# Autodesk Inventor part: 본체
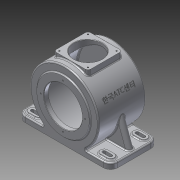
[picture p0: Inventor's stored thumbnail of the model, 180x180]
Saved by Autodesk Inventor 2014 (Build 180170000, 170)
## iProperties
Created: 2015-06
Part Number: 본체
Material: 알루미늄 6061
Document SubType Name: Modeling
Designer: basic
Density: 2.71 g/cm^3
Appearance: 알루미늄 - 평지
Mass: 3237.59 g
Surface Area: 2301.07 cm^2
Volume: 1194.68 cm^3
Author: basic
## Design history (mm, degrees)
sketch "스케치1"
  geometry: L1 (115, 7)-(-115, 7); L2 (-115, 7)-(-115, -7); L3 (-115, -7)-(115, -7); L4 (115, -7)-(115, 7); A1 r 85 centre (0, 78) between (46.733, 7) and (-46.733, 7); 3 further points
  constraints: 8 end point, 2 midpoint, 2 parallel, 2 point on circle, 2 point on line, 2 vertical alignment, 1 centre point, 1 horizontal, 1 horizontal alignment, 1 perpendicular
  dimensions: "d0" = 230 distance of L1.start L1.end; "d1" = 14 distance of L1.end L2.end; "d2" = 170 diameter of A1; "d3" = 85 distance from line of A1.centre L3
extrude "돌출1" new body sketch "스케치1" stored distance "d4" = 118; taper "d5" = 0 deg
sketch "스케치2"
  geometry: C1 r 65 at (0, 78); A1 r 85 centre (0, 78) between (46.733, 7) and (-46.733, 7) reference; 1 further point
  constraints: 1 centre point, 1 coincident
  dimensions: "d6" = 130 diameter of C1
extrude "돌출2" join sketch "스케치2" distance "d7" = 3; taper "d8" = 0 deg
sketch "스케치3"
  geometry: C1 r 65 at (0, -78); A1 r 85 centre (0, -78) between (-46.733, -7) and (46.733, -7) reference; 1 further point
  constraints: 1 centre point, 1 coincident
  dimensions: "d9" = 130 diameter of C1
extrude "돌출3" join sketch "스케치3" distance "d10" = 13; taper "d11" = 0 deg
node "작업 평면1"
sketch "스케치4"
  geometry: L1 (200, 0)-(30, 0) reference; L2 (157.5, -16.5)-(72.5, -16.5); L3 (72.5, -16.5)-(72.5, -101.5); L4 (72.5, -101.5)-(157.5, -101.5); L5 (157.5, -101.5)-(157.5, -16.5); 5 further points
  constraints: 8 end point, 2 midpoint, 2 parallel, 1 horizontal, 1 horizontal alignment, 1 perpendicular, 1 vertical alignment
  dimensions: "d13" = 85 distance of L4.end L3.end; "d14" = 85 distance of L3.end L2.end
extrude "돌출4" join sketch "스케치4" stored distance "d15" = 13; taper "d16" = 0 deg
sketch "스케치5"
  geometry: L1 (68.267, 0)-(68.267, 118) reference; L2 (0, 118)-(68.267, 118) reference; L3 (-161.733, 0)-(-161.733, 118) reference; L4 (68.267, 118)-(-161.733, 118) reference; L5 (68.267, 0)-(68.267, 118) reference; L6 (-161.733, 0)-(68.267, 0) reference; L7 (34.267, 109)-(50.267, 109); L8 (50.267, 91)-(34.267, 91); A1 r 9 centre (50.267, 100) between (50.267, 91) and (50.267, 109); A2 r 9 centre (34.267, 100) between (34.267, 109) and (34.267, 91); 1 further point
  constraints: 4 end point, 4 point on circle, 4 tangent, 2 centre point, 1 horizontal alignment
  dimensions: "d17" = 18 diameter of A1; "d18" = 18 diameter of A2; "d19" = 16 distance of A2.centre A1.centre; "d20" = 18 distance from line of A1.centre L1; "d21" = 18 distance from line of L2 A1.centre
extrude "돌출5" join sketch "스케치5" distance "d22" = 3; taper "d23" = 0 deg
sketch "스케치6"
  geometry: L1 (50.267, 109)-(34.267, 109) reference; L2 (34.267, 104)-(50.267, 104); L3 (50.267, 96)-(34.267, 96); A1 r 9 centre (34.267, 100) between (34.267, 109) and (34.267, 91) reference; A2 r 9 centre (50.267, 100) between (50.267, 91) and (50.267, 109) reference; A3 r 4 centre (50.267, 100) between (50.267, 96) and (50.267, 104); A4 r 4 centre (34.267, 100) between (34.267, 104) and (34.267, 96); 1 further point
  constraints: 4 end point, 4 point on circle, 3 tangent, 2 centre point, 2 coincident, 1 parallel
  dimensions: "d24" = 8 diameter of A3; "d25" = 8 diameter of A4
extrude "돌출6" cut sketch "스케치6" stored distance "d26" = 3; taper "d27" = 0 deg
sketch "스케치7"
  geometry: L1 (115, 7)-(46.733, 7) reference; L2 (-46.733, 7)-(-115, 7) reference; L3 (-115, 7)-(-115, -7) reference; L4 (-115, -7)-(115, -7) reference; L5 (115, -7)-(115, 7) reference; L6 (-109, 7)-(-84.87, 73.297); C1 r 65 at (0, 78) reference; A1 r 85 centre (0, 78) between (46.733, 7) and (-46.733, 7) reference; 1 further point
  constraints: 2 end point, 1 point on circle, 1 point on line
  dimensions: "d28" = 6 distance from line of L3 L6.start; "d29" = 110 deg angle of L2 L6
extrude "돌출7" join sketch "스케치7" stored distance "d30" = 15; taper "d31" = 0 deg
sketch "스케치8"
  geometry: L1 (115, 7)-(46.733, 7) reference; L2 (-46.733, 7)-(-115, 7) reference; L3 (-115, 7)-(-115, -7) reference; L4 (-115, -7)-(115, -7) reference; L5 (115, -7)-(115, 7) reference; C1 r 65 at (0, 78) reference; C2 r 77 at (0, 78); A1 r 85 centre (0, 78) between (46.733, 7) and (-46.733, 7) reference; 1 further point
  constraints: 1 centre point, 1 coincident
  dimensions: "d32" = 154 diameter of C2
extrude "돌출8" cut sketch "스케치8" stored distance "d33" = 102; taper "d34" = 0 deg
sketch "스케치9"
  geometry: C1 r 65 at (0, 0) reference; C2 r 47.5 at (0, 0); 1 further point
  constraints: 1 centre point, 1 coincident
  dimensions: "d35" = 95 diameter of C2
extrude "돌출9" cut sketch "스케치9" distance "d36" = 11; taper "d37" = 0 deg
sketch "스케치10"
  geometry: L1 (7.5, 73.297)-(7.5, 7) reference; L2 (59, 7)-(7.5, 7) reference; L3 (59, 7)-(59, 7) reference; L4 (-59, 7)-(59, 7) reference; L5 (-59, 7)-(-59, 7) reference; L6 (-7.5, 7)-(-59, 7) reference; L7 (-7.5, 7)-(-7.5, 73.297) reference; L8 (-7.5, 73.297)-(7.5, 73.297) reference; L9 (-42.5, 151.612)-(42.5, 151.612) reference; L10 (42.5, 151.612)-(42.5, 151.612) reference; L11 (42.5, 151.612)-(-42.5, 151.612) reference; L12 (-42.5, 151.612)-(-42.5, 151.612) reference; L13 (51, 1)-(51, 155) reference; L14 (-51, 125.5)-(-51, 30.5) reference; L15 (-62, 30.5)-(-62, 125.5) reference; L16 (47.5, 107.368)-(47.5, 78); L17 (47.5, 78)-(51, 78); L18 (51, 78)-(51, 109); L19 (51, 109)-(47.5, 107.368); 2 further points
  constraints: 8 end point, 1 horizontal, 1 horizontal alignment, 1 midpoint, 1 parallel, 1 point on line, 1 vertical
  dimensions: "d38" = 62 diameter of L18.end L17; "d39" = 115 deg angle of L13 L19; "d40" = 3.5 distance of L16.end L17.end
revolve "회전1" sketch "스케치10" stored, may be unused: angle "d41" = 90 deg
sketch "스케치11"
  geometry: C1 r 47.5 at (0, 0) reference; C2 r 23.5 at (0, 0); 1 further point
  constraints: 1 centre point, 1 coincident
  dimensions: "d42" = 47 diameter of C2
extrude "돌출10" cut sketch "스케치11" distance "d43" = 14; taper "d44" = 0 deg
sketch "스케치12"
  geometry: C1 r 23.5 at (0, 0) reference; C2 r 15 at (0, 0); 1 further point
  constraints: 1 centre point, 1 coincident
  dimensions: "d45" = 30 diameter of C2
extrude "돌출11" cut sketch "스케치12" distance "d46" = 3; taper "d47" = 0 deg
fillet "모깎기1" dims "d48" = 3, "d49" = 0.3
sketch "스케치13"
  geometry: C1 r 35 at (-115, -59); 1 further point
  constraints: 1 centre point, 1 coincident
  dimensions: "d50" = 70 diameter of C1
extrude "돌출12" cut sketch "스케치13" distance "d51" = 50; taper "d52" = 0 deg
sketch "스케치14"
  geometry: L1 (-150.5, -23.5)-(-79.5, -23.5); L2 (-79.5, -23.5)-(-79.5, -94.5); L3 (-79.5, -94.5)-(-150.5, -94.5); L4 (-150.5, -94.5)-(-150.5, -23.5); C1 r 35 at (-115, -59) reference; 3 further points
  constraints: 8 end point, 2 midpoint, 2 parallel, 1 coincident, 1 horizontal, 1 horizontal alignment, 1 perpendicular, 1 vertical alignment
  dimensions: "d53" = 71 distance of L2.end L3.end; "d54" = 71 distance of L1.end L2.end
hole "구멍1" sketch "스케치14" at (-79.5, -23.5) diameter "d55" = 3.242; stored, may be unused: countersink angle "d59" = 90 deg, drill point angle "d61" = 118 deg; dims "d56" = 10, "d57" = 47, "d58" = 14, "d60" = 13
sketch "스케치15"
  geometry: C1 r 47.5 at (0, 0) reference; 2 further points
  constraints: 1 vertical alignment
  dimensions: "d68" = 55 distance of C1.centre point (0, 55)
hole "구멍2" sketch "스케치15" at (0, 55) diameter "d69" = 3.242; stored, may be unused: countersink angle "d73" = 90 deg, drill point angle "d75" = 118 deg; dims "d70" = 11, "d71" = 47, "d72" = 14, "d74" = 13
fillet "모깎기2" dims "d79" = 7.5
fillet "모깎기3" dims "d80" = 7
fillet "모깎기6" dims "d83" = 18
fillet "모깎기7" dims "d84" = 3
fillet "모깎기8" dims "d85" = 3
fillet "모깎기9" dims "d86" = 3
fillet "모깎기10" dims "d87" = 3
fillet "모깎기11" dims "d88" = 3
fillet "모깎기12" dims "d89" = 3
fillet "모깎기13" dims "d90" = 3
node "작업 평면4"
  node "작업 평면3"
sketch "스케치16"
  geometry: L1 (11, 47.5)-(11, -47.5) reference; L2 (-26.8, 0)-(160.8, 0) reference; L3 (134, 62)-(134, -62) reference; L4 (0, 65)-(0, -65) reference; L5 (3, -79.424)-(3, 82) reference; L6 (121, 82)-(121, -79.424) reference; L7 (118, -82.329)-(118, 85) reference; 7 further points; 1 other entity
  constraints: 1 horizontal alignment, 1 midpoint, 1 vertical alignment, 2 other
feature "엠보싱1" sketch "스케치16" dims "d94" = 0.5, "d95" = 0
chamfer "모따기1" distance "d96" = 1; stored, may be unused: second distance "d97" = 2, angle "d98" = 45 deg
fillet "모깎기14" dims "d99" = 3
node "솔리드1"
mirror "대칭1"
mirror "대칭2"
pattern_linear "직사각형 패턴1" dims "d64" = 71, "d67" = 71
pattern_circular "원형 패턴1" dims angle "d77" = 360 deg
mirror "대칭3"
node "투영된 루프1"
node "투영된 루프2"
node "투영된 루프3"
node "투영된 루프4"
node "투영된 루프5"
node "작업 평면2"
node "작업축1"
node "투영된 루프6"
other parameters: "d12" = -173, "d91" = -85, "d92" = 65 deg, "d93" = -166
